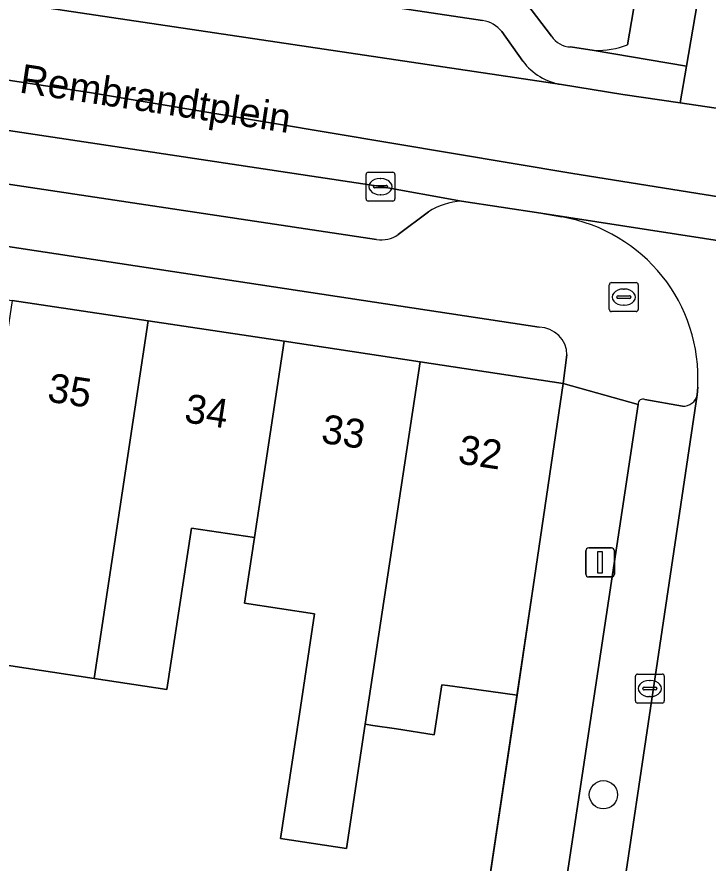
# Model space of a CAD drawing. Extents: x 162172 to 163187, y 382874 to 383685.
# Drawn here: x 162960.56 to 162984.46, y 383251.64 to 383280.9 of the extents above; entities that cross this region are included whole.
import ezdxf

# ---------------------------------------------------------------- set-up
doc = ezdxf.new("R2010")
doc.units = 0
for name, color, linetype in [('IMGEO_Boom', 7, 'Continuous'), ('IMGEO_Brandkraan', 7, 'Continuous'), ('IMGEO_Erf', 7, 'Continuous'), ('IMGEO_Groenvoorziening', 7, 'Continuous'), ('IMGEO_Kolk', 7, 'Continuous'), ('IMGEO_Lichtmast', 7, 'Continuous'), ('IMGEO_Muur', 7, 'Continuous'), ('IMGEO_Openbare_ruimte_label', 7, 'Continuous'), ('IMGEO_Pand', 7, 'Continuous'), ('IMGEO_Pand_nummerreeks', 7, 'Continuous'), ('IMGEO_Parkeervlak_open', 7, 'Continuous'), ('IMGEO_Rijbaan_lokaal_gesloten', 7, 'Continuous'), ('IMGEO_Rijbaan_lokaal_open', 7, 'Continuous'), ('IMGEO_Voetpad_open', 7, 'Continuous')]:
    doc.layers.add(name, color=color, linetype=linetype)

msp = doc.modelspace()

# ---------------------------------------------------------------- linework, layer by layer
at = {"layer": 'IMGEO_Boom'}
msp.add_circle((162980.845, 383254.002), 0.489, dxfattribs=at)
at = {"layer": 'IMGEO_Brandkraan'}
for p, q in [((162981.048, 383270.782), (162981.048, 383271.634)), ((162981.123, 383271.708), (162981.975, 383271.708)), ((162982.049, 383271.634), (162982.049, 383270.782)), ((162981.307, 383271.202), (162981.307, 383271.214)), ((162981.35, 383271.251), (162981.748, 383271.251)), ((162981.536, 383271.488), (162981.561, 383271.488)), ((162981.791, 383271.214), (162981.791, 383271.202)), ((162981.745, 383271.165), (162981.347, 383271.165)), ((162981.559, 383270.928), (162981.534, 383270.928)), ((162981.975, 383270.708), (162981.123, 383270.708))]:
    msp.add_line(p, q, dxfattribs=at)
for points in [[(162981.048, 383270.782), (162981.048, 383271.634)], [(162981.123, 383271.708), (162981.975, 383271.708)], [(162982.049, 383271.634), (162982.049, 383270.782)], [(162981.975, 383270.708), (162981.123, 383270.708)]]:
    msp.add_lwpolyline(points, dxfattribs=at)
for centre, radius, start, end in [((162981.125, 383271.632), 0.0765, 91.552, 178.448), ((162981.125, 383271.632), 0.0765, 91.552, 178.448), ((162981.973, 383271.632), 0.0765, 1.552, 88.448), ((162981.973, 383271.632), 0.0765, 1.552, 88.448), ((162981.347, 383271.211), 0.0403, 85.8775, 175.7526), ((162981.344, 383271.201), 0.0366, 178.938, 274.7102), ((162981.748, 383271.208), 0.043, 264.8664, 352.4533), ((162981.752, 383271.213), 0.0386, 1.7309, 96.639), ((162981.125, 383270.784), 0.0765, 181.552, 268.448), ((162981.125, 383270.784), 0.0765, 181.552, 268.448), ((162981.973, 383270.784), 0.0765, 271.552, 358.448), ((162981.973, 383270.784), 0.0765, 271.552, 358.448)]:
    msp.add_arc(centre, radius, start, end, dxfattribs=at)
for centre, major_axis, ratio, start_param, end_param in [((162981.535, 383271.208), (-0.387, 0.002), 0.722429, 4.712389, 7.853982), ((162981.56, 383271.208), (-0.39, 0.002), 0.717154, 1.570796, 4.712389)]:
    msp.add_ellipse(centre, major_axis=major_axis, ratio=ratio, start_param=start_param, end_param=end_param, dxfattribs=at)
at = {"layer": 'IMGEO_Erf'}
for points in [[(162978.626, 383270.167), (162932.146, 383277.218)], [(162930.093, 383276.055), (162930.093, 383275.66), (162932.35, 383275.32), (162936.892, 383274.636), (162941.594, 383273.928), (162946.296, 383273.22), (162950.997, 383272.512), (162955.7, 383271.804), (162960.402, 383271.096), (162965.104, 383270.388), (162969.805, 383269.68), (162974.508, 383268.972), (162979.454, 383268.227), (162979.583, 383269.208)], [(162975.94, 383244.627), (162977.859, 383257.448), (162976.037, 383257.698), (162975.454, 383257.778), (162975.258, 383257.805), (162974.997, 383256.078), (162973.686, 383256.277), (162972.872, 383256.4), (162972.609, 383256.44), (162971.959, 383252.146), (162969.683, 383252.491), (162970.334, 383256.785), (162970.856, 383260.259), (162968.434, 383260.626), (162968.777, 383262.893), (162966.599, 383263.223), (162965.753, 383257.637), (162963.232, 383258.02), (162960.89, 383258.376), (162958.532, 383258.734)]]:
    msp.add_lwpolyline(points, dxfattribs=at)
msp.add_arc((162978.611, 383269.195), 0.972, 0.7406, 89.1398, dxfattribs=at)
at = {"layer": 'IMGEO_Groenvoorziening'}
for points in [[(162984.978, 383286.545), (162983.72, 383279.193), (162983.503, 383277.926), (162992.43, 383276.599), (162990.743, 383289.153)], [(162981.68, 383279.931), (162983.101, 383288.276)], [(162978.2, 383281.354), (162979.052, 383280.229)], [(162979.709, 383279.858), (162980.528, 383279.739)]]:
    msp.add_lwpolyline(points, dxfattribs=at)
for centre, radius, start, end in [((162979.727, 383280.657), 0.799, 212.3637, 268.7305), ((162980.606, 383282.825), 3.087, 268.5588, 290.3658)]:
    msp.add_arc(centre, radius, start, end, dxfattribs=at)
at = {"layer": 'IMGEO_Kolk'}
for p, q in [((162972.635, 383274.601), (162972.635, 383275.453)), ((162972.71, 383275.527), (162973.562, 383275.527)), ((162973.123, 383275.307), (162973.148, 383275.307)), ((162973.636, 383275.453), (162973.636, 383274.601)), ((162972.894, 383275.021), (162972.894, 383275.033)), ((162972.937, 383275.07), (162973.335, 383275.07)), ((162973.378, 383275.033), (162973.378, 383275.021)), ((162973.332, 383274.984), (162972.934, 383274.984)), ((162973.146, 383274.747), (162973.121, 383274.747)), ((162973.562, 383274.527), (162972.71, 383274.527)), ((162981.948, 383257.248), (162981.948, 383258.1)), ((162982.023, 383258.174), (162982.875, 383258.174)), ((162982.949, 383258.1), (162982.949, 383257.248)), ((162982.436, 383257.954), (162982.461, 383257.954)), ((162982.207, 383257.668), (162982.207, 383257.68)), ((162982.645, 383257.631), (162982.247, 383257.631)), ((162982.25, 383257.717), (162982.648, 383257.717)), ((162982.691, 383257.68), (162982.691, 383257.668)), ((162982.875, 383257.174), (162982.023, 383257.174)), ((162982.459, 383257.394), (162982.434, 383257.394))]:
    msp.add_line(p, q, dxfattribs=at)
for points in [[(162972.635, 383274.601), (162972.635, 383275.453)], [(162972.71, 383275.527), (162973.562, 383275.527)], [(162973.636, 383275.453), (162973.636, 383274.601)], [(162973.562, 383274.527), (162972.71, 383274.527)], [(162981.948, 383257.248), (162981.948, 383258.1)], [(162982.023, 383258.174), (162982.875, 383258.174)], [(162982.949, 383258.1), (162982.949, 383257.248)], [(162982.875, 383257.174), (162982.023, 383257.174)]]:
    msp.add_lwpolyline(points, dxfattribs=at)
for centre, radius, start, end in [((162972.712, 383275.451), 0.0765, 91.552, 178.448), ((162972.712, 383275.451), 0.0765, 91.552, 178.448), ((162973.56, 383275.451), 0.0765, 1.552, 88.448), ((162973.56, 383275.451), 0.0765, 1.552, 88.448), ((162972.934, 383275.03), 0.0403, 85.8775, 175.7526), ((162972.931, 383275.02), 0.0366, 178.938, 274.7102), ((162973.335, 383275.027), 0.043, 264.8664, 352.4533), ((162973.339, 383275.032), 0.0386, 1.7309, 96.639), ((162972.712, 383274.603), 0.0765, 181.552, 268.448), ((162972.712, 383274.603), 0.0765, 181.552, 268.448), ((162973.56, 383274.603), 0.0765, 271.552, 358.448), ((162973.56, 383274.603), 0.0765, 271.552, 358.448), ((162982.025, 383258.098), 0.0765, 91.552, 178.448), ((162982.025, 383258.098), 0.0765, 91.552, 178.448), ((162982.873, 383258.098), 0.0765, 1.552, 88.448), ((162982.873, 383258.098), 0.0765, 1.552, 88.448), ((162982.247, 383257.677), 0.0403, 85.8775, 175.7526), ((162982.244, 383257.667), 0.0366, 178.938, 274.7102), ((162982.648, 383257.674), 0.043, 264.8664, 352.4533), ((162982.652, 383257.679), 0.0386, 1.7309, 96.639), ((162982.025, 383257.25), 0.0765, 181.552, 268.448), ((162982.025, 383257.25), 0.0765, 181.552, 268.448), ((162982.873, 383257.25), 0.0765, 271.552, 358.448), ((162982.873, 383257.25), 0.0765, 271.552, 358.448)]:
    msp.add_arc(centre, radius, start, end, dxfattribs=at)
for centre, major_axis, ratio, start_param, end_param in [((162973.122, 383275.027), (-0.387, 0.002), 0.722429, 4.712389, 7.853982), ((162973.147, 383275.027), (-0.39, 0.002), 0.717154, 1.570796, 4.712389), ((162982.435, 383257.674), (-0.387, 0.002), 0.722429, 4.712389, 7.853982), ((162982.46, 383257.674), (-0.39, 0.002), 0.717154, 1.570796, 4.712389)]:
    msp.add_ellipse(centre, major_axis=major_axis, ratio=ratio, start_param=start_param, end_param=end_param, dxfattribs=at)
at = {"layer": 'IMGEO_Lichtmast'}
for p, q in [((162980.234, 383261.634), (162980.234, 383262.434)), ((162980.234, 383262.434), (162980.234, 383261.634)), ((162980.334, 383262.534), (162981.124, 383262.534)), ((162981.124, 383262.534), (162980.334, 383262.534)), ((162981.224, 383262.434), (162981.224, 383261.634)), ((162981.224, 383261.634), (162981.224, 383262.434)), ((162981.124, 383261.534), (162980.334, 383261.534)), ((162980.334, 383261.534), (162981.124, 383261.534))]:
    msp.add_line(p, q, dxfattribs=at)
msp.add_lwpolyline([(162980.654, 383262.409), (162980.804, 383262.409), (162980.804, 383261.659), (162980.654, 383261.659), (162980.654, 383262.409)], dxfattribs=at)
for centre, start, end in [((162980.334, 383262.434), 90, 180), ((162980.334, 383262.434), 90, 180), ((162981.124, 383262.434), 0, 90), ((162981.124, 383262.434), 360, 90), ((162980.334, 383261.634), 180, 270), ((162980.334, 383261.634), 180, 270), ((162981.124, 383261.634), 270, 0), ((162981.124, 383261.634), 270, 0)]:
    msp.add_arc(centre, 0.1, start, end, dxfattribs=at)
at = {"layer": 'IMGEO_Muur'}
msp.add_lwpolyline([(162975.94, 383244.627), (162978.458, 383261.497)], dxfattribs=at)
at = {"layer": 'IMGEO_Pand'}
for points in [[(162965.104, 383270.388), (162960.402, 383271.096), (162959.377, 383264.319), (162958.532, 383258.734), (162960.89, 383258.376), (162963.232, 383258.02)], [(162968.777, 383262.893), (162969.805, 383269.68), (162965.104, 383270.388), (162963.232, 383258.02), (162965.753, 383257.637), (162966.599, 383263.223)], [(162974.508, 383268.972), (162969.805, 383269.68), (162968.777, 383262.893), (162968.434, 383260.626), (162970.856, 383260.259), (162970.334, 383256.785), (162969.683, 383252.491), (162971.959, 383252.146), (162972.609, 383256.44)], [(162978.458, 383261.497), (162979.454, 383268.227), (162974.508, 383268.972), (162972.609, 383256.44), (162972.872, 383256.4), (162973.686, 383256.277), (162974.997, 383256.078), (162975.258, 383257.805), (162975.454, 383257.778), (162976.037, 383257.698), (162977.859, 383257.448)]]:
    msp.add_lwpolyline(points, close=True, dxfattribs=at)
at = {"layer": 'IMGEO_Parkeervlak_open'}
for points in [[(162976.668, 383280.776), (162946.939, 383285.226)], [(162943.619, 383283.897), (162979.394, 383278.554)], [(162975.936, 383274.527), (162973.133, 383275.028), (162935.314, 383280.725)], [(162978.06, 383279.363), (162977.332, 383280.388)], [(162938.244, 383278.42), (162972.998, 383273.201)], [(162973.749, 383273.373), (162974.795, 383274.153)], [(162961.044, 383124.266), (162965.268, 383143.121), (162966.059, 383147.348), (162966.461, 383150.066), (162972.803, 383192.564), (162973.231, 383195.286), (162979.423, 383236.668), (162979.85, 383239.428), (162984.085, 383267.824)], [(162982.044, 383267.498), (162978.175, 383241.837)], [(162983.576, 383267.441), (162982.281, 383267.668)]]:
    msp.add_lwpolyline(points, dxfattribs=at)
for centre, radius, start, end in [((162976.481, 383279.693), 1.099, 39.2213, 80.1801), ((162979.754, 383280.652), 2.129, 217.2667, 260.2641), ((162976.056, 383272.233), 2.297, 92.9961, 123.3003), ((162973.167, 383274.189), 1.002, 260.2887, 305.511), ((162983.614, 383267.92), 0.481, 265.4501, 348.4696), ((162982.211, 383267.516), 0.168, 65.227, 186.0767)]:
    msp.add_arc(centre, radius, start, end, dxfattribs=at)
at = {"layer": 'IMGEO_Rijbaan_lokaal_gesloten'}
for points in [[(163000, 383275.499), (162999.752, 383275.522), (162999.504, 383275.548), (162992.43, 383276.599), (162983.503, 383277.926), (162981.518, 383278.216), (162979.394, 383278.554), (162943.619, 383283.897), (162942.607, 383284.048)], [(163040.344, 383282.562), (163020.844, 383276.695), (163009.736, 383273.624), (163003.62, 383272.424), (163000.382, 383272.424), (162997.504, 383272.791), (162988.869, 383274.025), (162979.785, 383275.484), (162963.075, 383278.288), (162940.869, 383281.654)], [(162940.869, 383281.654), (162963.075, 383278.288), (162979.785, 383275.484), (162988.869, 383274.025), (162997.504, 383272.791), (163000.382, 383272.424), (163003.62, 383272.424), (163009.736, 383273.624), (163020.844, 383276.695), (163040.344, 383282.562)], [(162932.962, 383280.637), (162934.995, 383280.773), (162935.314, 383280.725), (162973.133, 383275.028), (162975.936, 383274.527), (162978.681, 383274.105), (162990.964, 383272.214), (162992.596, 383271.991), (162993.768, 383271.831), (162996.284, 383271.485), (163000, 383271.063), (163000.379, 383271.02)]]:
    msp.add_lwpolyline(points, dxfattribs=at)
at = {"layer": 'IMGEO_Rijbaan_lokaal_open'}
for points in [[(162990.964, 383272.214), (162978.681, 383274.105), (162979.404, 383273.98)], [(162984.104, 383268.09), (162984.085, 383267.824), (162979.85, 383239.428), (162983.074, 383238.918), (162987.312, 383267.33)]]:
    msp.add_lwpolyline(points, dxfattribs=at)
msp.add_arc((162978.458, 383268.405), 5.655, 356.807, 80.3701, dxfattribs=at)
at = {"layer": 'IMGEO_Voetpad_open'}
for points in [[(162983.101, 383288.276), (162981.68, 383279.931)], [(162980.528, 383279.739), (162983.72, 383279.193), (162984.978, 383286.545)], [(162946.939, 383285.226), (162976.668, 383280.776)], [(162979.052, 383280.229), (162978.2, 383281.354)], [(162977.332, 383280.388), (162978.06, 383279.363)], [(162979.394, 383278.554), (162981.518, 383278.216), (162983.503, 383277.926), (162983.72, 383279.193), (162980.528, 383279.739)], [(162980.528, 383279.739), (162979.709, 383279.858)], [(162972.998, 383273.201), (162938.244, 383278.42)], [(162932.146, 383277.218), (162978.626, 383270.167)], [(162979.404, 383273.98), (162978.681, 383274.105), (162975.936, 383274.527)], [(162974.795, 383274.153), (162973.749, 383273.373)], [(162979.583, 383269.208), (162979.454, 383268.227), (162982.044, 383267.498)], [(162978.175, 383241.837), (162982.044, 383267.498), (162979.454, 383268.227), (162978.458, 383261.497), (162977.859, 383257.448), (162975.94, 383244.627), (162975.499, 383241.819), (162975.456, 383241.535), (162975.284, 383240.385), (162968.157, 383192.874), (162967.996, 383191.801), (162961.62, 383149.29), (162961.571, 383149.008), (162961.307, 383147.483), (162961.288, 383147.372), (162960.945, 383145.438), (162956.262, 383123.982), (162952.155, 383121.467), (162959.964, 383119.516), (162960.241, 383120.675), (162961.044, 383124.266)], [(162984.085, 383267.824), (162984.104, 383268.09)], [(162982.281, 383267.668), (162983.576, 383267.441)]]:
    msp.add_lwpolyline(points, dxfattribs=at)
for centre, radius, start, end in [((162976.481, 383279.693), 1.099, 39.2213, 80.1801), ((162979.727, 383280.657), 0.799, 212.3637, 268.7305), ((162980.606, 383282.825), 3.087, 268.5588, 290.3658), ((162979.754, 383280.652), 2.129, 217.2667, 260.2641), ((162976.056, 383272.233), 2.297, 92.9961, 123.3003), ((162978.458, 383268.405), 5.655, 356.807, 80.3701), ((162973.167, 383274.189), 1.002, 260.2887, 305.511), ((162978.611, 383269.195), 0.972, 0.7406, 89.1398), ((162983.614, 383267.92), 0.481, 265.4501, 348.4696), ((162982.211, 383267.516), 0.168, 65.227, 186.0767)]:
    msp.add_arc(centre, radius, start, end, dxfattribs=at)

# ---------------------------------------------------------------- texts
at = {"layer": 'IMGEO_Openbare_ruimte_label'}
msp.add_text('Rembrandtplein', height=1, rotation=351.4324, dxfattribs=at).set_placement((162960.619, 383278.287))
at = {"layer": 'IMGEO_Pand_nummerreeks'}
for s, rotation, p in [('35', 351.4343, (162961.585, 383267.602)), ('34', 351.4361, (162966.317, 383266.888)), ('33', 351.4343, (162971.05, 383266.176)), ('32', 351.4343, (162975.779, 383265.464))]:
    msp.add_text(s, height=1, rotation=rotation, dxfattribs=at).set_placement(p)

doc.saveas('drawing.dxf')
